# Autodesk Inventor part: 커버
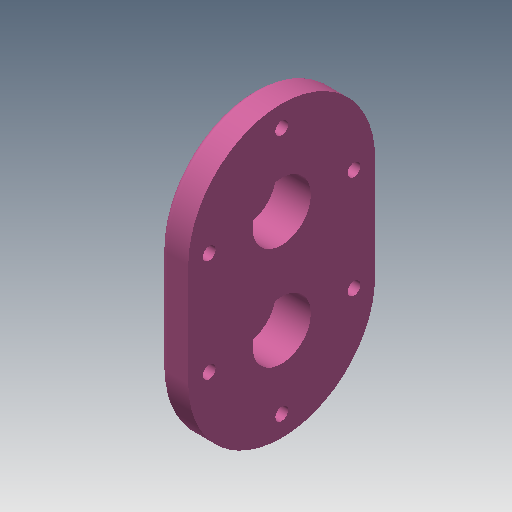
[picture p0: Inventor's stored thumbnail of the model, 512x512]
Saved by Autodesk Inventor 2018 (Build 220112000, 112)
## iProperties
Created: 2019-03
Part Number: 커버
Material: 알루미늄 6061
Document SubType Name: Modeling
Designer: mduedu
Density: 1 g/cm^3
Appearance: 분홍색
Author: mduedu
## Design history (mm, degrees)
sketch "스케치1"
  geometry: L1 (-62, 40)-(62, 40); L2 (62, 40)-(62, -40); L3 (62, -40)-(-62, -40); L4 (-62, -40)-(-62, 40); L5 (-62, 40)-(62, -40); L6 (62, 40)-(-62, -40); 1 further point
  constraints: 12 end point, 2 midpoint, 2 parallel, 1 horizontal, 1 perpendicular
  dimensions: "d59" = 124 distance of L2.end L3.end; "d60" = 80 distance of L1.end L2.end
extrude "돌출1" new body sketch "스케치1" distance "d4" = 12; taper "d5" = 0 deg
fillet "모깎기4"
fillet "모깎기5"
sketch "스케치2"
  geometry: L1 (-20, -22)-(20, -22); L2 (20, -22)-(20, 22); L3 (20, 22)-(-20, 22); L4 (-20, 22)-(-20, -22); L5 (-20, -22)-(20, 22); L6 (20, -22)-(-20, 22); 3 further points
  constraints: 12 end point, 4 midpoint, 2 horizontal alignment, 2 parallel, 1 horizontal, 1 perpendicular, 4 other
  dimensions: "d6" = 40 distance between parallel lines of L2 L4; "d8" = 44 distance between parallel lines of L1 L3
extrude "돌출2" join sketch "스케치2" distance "d9" = 10; taper "d10" = 0 deg
fillet "모깎기2" dims "d12" = 3
sketch "스케치3"
  geometry: L1 (-31, -22)-(31, -22); L2 (31, -22)-(31, 22); L3 (31, 22)-(-31, 22); L4 (-31, 22)-(-31, -22); L5 (-31, -22)-(31, 22); L6 (31, -22)-(-31, 22); A1 r 31 centre (0, 22) between (31, 22) and (0, 53); A2 r 31 centre (0, -22) between (31, -22) and (0, -53); 7 further points
  constraints: 12 end point, 6 midpoint, 4 coincident, 4 point on circle, 2 centre point, 2 parallel, 2 vertical alignment, 1 horizontal, 1 perpendicular
  dimensions: "d76" = 44 distance between parallel lines of L1 L3; "d78" = 62 distance between parallel lines of L2 L4
hole "구멍2" sketch "스케치3" at (0, 53), (31, 22), (31, -22), (-31, -22), (-31, 22), (0, -53) diameter "d28" = 5.5; stored, may be unused: countersink angle "d32" = 90 deg, drill point angle "d34" = 118 deg; dims "d29" = 6, "d30" = 4, "d31" = 2, "d33" = 8
sketch "스케치10"
  geometry: L1 (40, -22)-(40, 22) reference; L2 (-40, 22)-(-40, -22) reference; L3 (23, -22)-(23, 22) reference; L4 (-23, 22)-(-23, -22) reference; C1 r 2.75 at (-31, 22) reference; C2 r 2.75 at (31, -22) reference; C3 r 2.75 at (0, 53) reference; C4 r 2.75 at (31, 22) reference; C5 r 2.75 at (-31, -22) reference; C6 r 2.75 at (0, -53) reference; A1 r 40 centre (0, -22) between (-40, -22) and (40, -22) reference; A2 r 40 centre (0, 22) between (40, 22) and (-40, 22) reference; A3 r 23 centre (0, -22) between (-23, -22) and (23, -22) reference; A4 r 23 centre (0, 22) between (23, 22) and (-23, 22) reference; 7 further points
  constraints: 6 coincident
hole "구멍5" sketch "스케치10" at (0, 53), (31, 22), (31, -22), (0, -53), (-31, -22), (-31, 22) diameter "d79" = 11; stored, may be unused: countersink angle "d83" = 90 deg, drill point angle "d85" = 0 deg; dims "d80" = 6, "d81" = 4, "d82" = 2, "d84" = 5.4
fillet "모깎기3" dims "d68" = 3
sketch "스케치6"
  geometry: C1 r 12.5 at (0, 22); 1 further point
  constraints: 1 centre point, 1 vertical alignment
  dimensions: "d43" = 25 diameter of C1; "d45" = 22 distance of C1.centre point (0, 0)
extrude "돌출5" cut sketch "스케치6" distance "d47" = 15; taper "d48" = 0 deg
node "솔리드1"
mirror "대칭1"
node "투영된 루프5"
